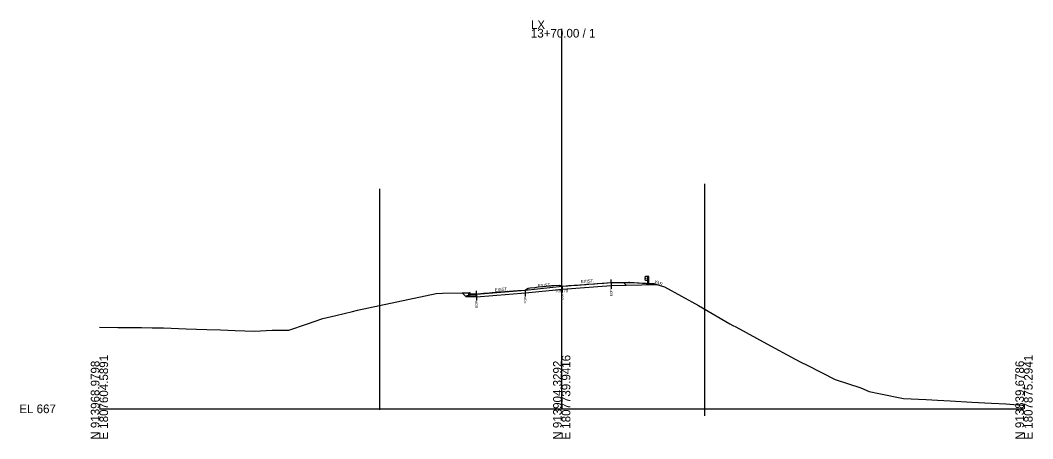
# Model space of a CAD drawing. Extents: x -26 to 1352, y -510 to 9596.
# Drawn here: x -25.7 to 302.8, y -509.7 to -374 of the extents above; entities that cross this region are included whole.
import ezdxf

# ---------------------------------------------------------------- set-up
doc = ezdxf.new("R2010")
doc.units = 0
for name, color, linetype in [('Exist Cross Section Cell', 7, 'Continuous'), ('Exist XS Center Line Elevation Label', 7, 'Continuous'), ('Exist XS Ground Line', 7, 'Continuous'), ('Old_Level_10', 7, 'Continuous'), ('Prop XS Ditch Slope Text', 7, 'Continuous'), ('Prop XS EOT Tick Mark', 7, 'Continuous'), ('Prop XS Exc Vertical Line 1', 7, 'Continuous'), ('Prop XS Exc Vertical Line 2', 7, 'Continuous'), ('Prop XS Finish Grade', 7, 'Continuous'), ('Prop XS Finish Grade Concrete', 7, 'Continuous'), ('Prop XS Finish Grade Earthwork', 7, 'Continuous'), ('Prop XS Finish Grade Paved Shoulder', 7, 'Continuous'), ('Prop XS Finish Grade Pavement', 7, 'Continuous'), ('Prop XS Guardrail', 7, 'Continuous'), ('Prop XS Pvmt Edge Slope', 7, 'Continuous'), ('Prop XS SE Text', 7, 'Continuous'), ('Prop XS Subgrade Earthwork', 7, 'Continuous'), ('Typical Curb CELL', 7, 'Continuous')]:
    doc.layers.add(name, color=color, linetype=linetype)

msp = doc.modelspace()

# ---------------------------------------------------------------- linework, layer by layer
at = {"layer": 'Exist Cross Section Cell'}
for p, q in [((150, -500), (150, -376.83)), ((0, -500), (150, -500)), ((150, -500), (300, -500))]:
    msp.add_line(p, q, dxfattribs=at)
at = {"layer": 'Exist XS Ground Line'}
msp.add_lwpolyline([(0, -473.48), (6, -473.62), (13.64, -473.63), (17.08, -473.7), (20.83, -473.79), (28.16, -474.03), (34.86, -474.28), (39.24, -474.44), (44.04, -474.62), (50.33, -474.81), (56.08, -474.46), (61.41, -474.45), (67.24, -472.52), (72.49, -470.72), (76.71, -469.75), (82.13, -468.4), (83.77, -468), (87.31, -467.23), (109.29, -462.57), (111.32, -462.5), (119.69, -462.37), (120.26, -462.9), (121.28, -462.86), (122.34, -462.79), (122.76, -462.75), (124.65, -462.51), (126.5, -462.37), (127.42, -462.29), (127.74, -462.27), (128.42, -462.21), (129.63, -462.12), (130.19, -462.07), (131.5, -461.97), (132.96, -461.87), (134.25, -461.77), (135.73, -461.66), (136.5, -461.61), (138.17, -461.5), (138.58, -461.16), (139.12, -460.85), (139.76, -460.78), (141.27, -460.62), (142.37, -460.5), (144.03, -460.33), (145.84, -460.15), (146.49, -460.08), (146.8, -460.05), (147.35, -460.02), (149.28, -459.9), (150.14, -460.27), (151.42, -460.16), (151.94, -460.11), (152.35, -460.07), (154, -459.95), (155.12, -459.87), (157.45, -459.69), (157.88, -459.66), (158.29, -459.63), (160.66, -459.46), (161.5, -459.4), (163.65, -459.23), (166.05, -459.07), (166.49, -459.07), (168.98, -459.03), (171.64, -458.95), (171.99, -458.94), (173.54, -459.07), (175.16, -459.2), (176.19, -459.28), (180.84, -459.65), (183.37, -460.47), (194.39, -466.5), (204.59, -472.42), (205.48, -472.94), (206.45, -473.47), (216.56, -478.98), (225.8, -483.87), (227.64, -484.84), (229.65, -485.86), (238.72, -490.45), (247.02, -493.24), (249.8, -494.36), (252.85, -494.99), (260.89, -496.62), (268.23, -496.93), (271.97, -497.23), (276.05, -497.41), (283.05, -497.82), (289.45, -498.12), (294.13, -498.37), (299.25, -498.77), (300, -498.83)], dxfattribs=at)
at = {"layer": 'Old_Level_10'}
for p, q in [((166.05, -459.07), (166.05, -461.12)), ((122.34, -462.79), (122.34, -464.84)), ((138.17, -461.5), (138.17, -463.55)), ((150.14, -460.27), (150.14, -462.32))]:
    msp.add_line(p, q, dxfattribs=at)
at = {"layer": 'Prop XS EOT Tick Mark'}
for p, q in [((166.05, -459.07), (166.05, -458.07)), ((122.34, -462.79), (122.34, -461.79))]:
    msp.add_line(p, q, dxfattribs=at)
at = {"layer": 'Prop XS Exc Vertical Line 1'}
msp.add_line((90.98, -500.32), (90.98, -428.67), dxfattribs=at)
at = {"layer": 'Prop XS Exc Vertical Line 2'}
msp.add_line((196.44, -502.27), (196.44, -427.04), dxfattribs=at)
at = {"layer": 'Prop XS Finish Grade'}
for p, q in [((170.06, -459), (171.63, -459.06)), ((117.65, -462.4), (119.84, -462.37))]:
    msp.add_line(p, q, dxfattribs=at)
at = {"layer": 'Prop XS Finish Grade Concrete'}
for p, q in [((119.84, -462.37), (120.1, -462.37)), ((120.34, -462.62), (120.34, -462.61)), ((122.34, -462.79), (120.59, -462.86))]:
    msp.add_line(p, q, dxfattribs=at)
for centre, start, end in [((120.1, -462.61), 0, 90), ((120.58, -462.62), 180, 272.3845)]:
    msp.add_arc(centre, 0.24, start, end, dxfattribs=at)
at = {"layer": 'Prop XS Finish Grade Earthwork'}
for p, q in [((171.63, -459.06), (177.36, -459.3)), ((177.36, -459.3), (180.05, -459.41)), ((180.05, -459.41), (180.84, -459.65))]:
    msp.add_line(p, q, dxfattribs=at)
at = {"layer": 'Prop XS Finish Grade Paved Shoulder'}
msp.add_line((166.05, -459.07), (170.06, -459), dxfattribs=at)
at = {"layer": 'Prop XS Finish Grade Pavement'}
for p, q in [((150.14, -460.27), (166.05, -459.07)), ((122.34, -462.79), (138.17, -461.5)), ((138.17, -461.5), (150.14, -460.27))]:
    msp.add_line(p, q, dxfattribs=at)
at = {"layer": 'Prop XS Guardrail'}
for p, q in [((177, -457.35), (176.97, -457.41)), ((176.97, -457.41), (177, -457.47)), ((177, -457.96), (176.97, -458.02)), ((176.97, -458.02), (177, -458.08)), ((177.29, -457.15), (177, -457.35)), ((177, -457.47), (177.29, -457.67)), ((177.29, -457.76), (177, -457.96)), ((177, -458.08), (177.29, -458.28)), ((177.79, -457.15), (177.29, -457.15)), ((177.29, -457.67), (177.29, -457.76)), ((177.29, -458.28), (177.79, -458.28)), ((178.29, -457.15), (177.79, -457.15)), ((177.79, -457.15), (177.79, -459.65)), ((178.29, -459.65), (178.29, -457.15))]:
    msp.add_line(p, q, dxfattribs=at)
at = {"layer": 'Prop XS Pvmt Edge Slope'}
for p, q in [((170.06, -459), (170.86, -459.9)), ((119.2, -463.37), (118.96, -463.71)), ((119.52, -463.37), (119.2, -463.37)), ((119.84, -463.37), (119.52, -463.37))]:
    msp.add_line(p, q, dxfattribs=at)
at = {"layer": 'Prop XS Subgrade Earthwork'}
for p, q in [((166.09, -459.99), (170.86, -459.9)), ((170.86, -459.9), (180.84, -459.65)), ((117.65, -462.4), (118.96, -463.71)), ((122.34, -463.71), (138.26, -462.41)), ((138.26, -462.41), (150.22, -461.18)), ((150.22, -461.18), (166.09, -459.99)), ((122.34, -463.71), (118.96, -463.71))]:
    msp.add_line(p, q, dxfattribs=at)
at = {"layer": 'Typical Curb CELL'}
for p, q in [((119.84, -463.37), (119.84, -462.37)), ((122.34, -463.37), (122.34, -462.79)), ((119.84, -463.37), (122.34, -463.37))]:
    msp.add_line(p, q, dxfattribs=at)

# ---------------------------------------------------------------- texts
at = {"layer": 'Exist Cross Section Cell'}
for s, p in [('LX', (140, -376.83)), ('13+70.00 / 1', (140, -379.63)), ('EL 667', (-26, -501.4))]:
    msp.add_text(s, height=2.8, dxfattribs=at).set_placement(p)
for s, p in [('E 1807604.5891', (2.8, -510)), ('E 1807739.9416', (152.8, -510)), ('E 1807875.2941', (302.8, -510)), ('N 913968.9798', (0, -510)), ('N 913904.3292', (150, -510)), ('N 913839.6786', (300, -510))]:
    msp.add_text(s, height=2.8, rotation=90, dxfattribs=at).set_placement(p)
at = {"layer": 'Exist XS Center Line Elevation Label'}
msp.add_text('706.79', height=1, dxfattribs=at).set_placement((147.87, -462.21))
at = {"layer": 'Old_Level_10'}
for p in [(150.53, -464.72), (166.44, -463.52), (122.74, -467.24), (138.57, -465.94)]:
    msp.add_text('EOP', height=0.787, rotation=90, dxfattribs=at).set_placement(p)
at = {"layer": 'Prop XS Ditch Slope Text'}
msp.add_text('VAR.', height=1, rotation=337.8997, dxfattribs=at).set_placement((179.88, -459.08))
at = {"layer": 'Prop XS SE Text'}
for p in [(142.3, -460.65), (156.24, -459.28), (128.3, -461.94)]:
    msp.add_text('EXIST.', height=1, rotation=4.5739, dxfattribs=at).set_placement(p)

doc.saveas('drawing.dxf')
